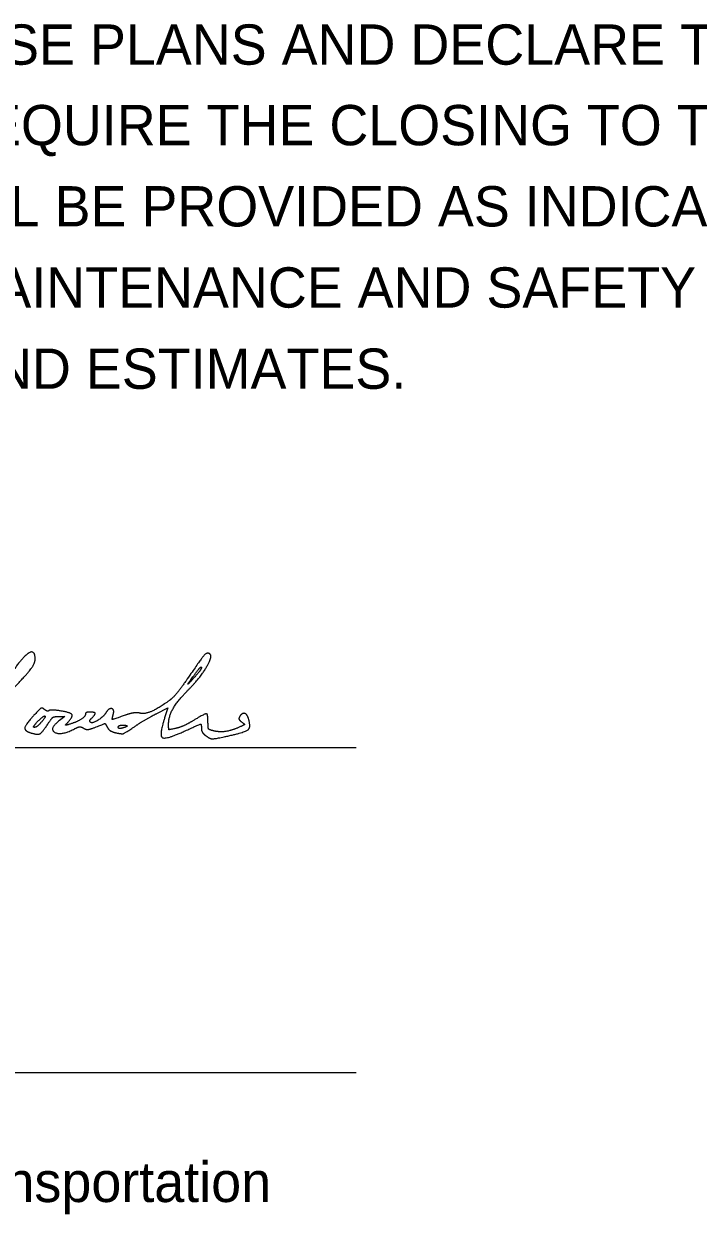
# Model space of a CAD drawing. Extents: x 0 to 44, y -23.8 to 22.
# Drawn here: x 26.858 to 29.2, y 6.74 to 10.877 of the extents above; entities that cross this region are included whole.
import ezdxf

# ---------------------------------------------------------------- set-up
doc = ezdxf.new("R2010")
doc.units = 0
for name, color, linetype in [('Default', 7, 'Continuous'), ('SH_Data', 7, 'Continuous'), ('SH_Text', 7, 'Continuous')]:
    doc.layers.add(name, color=color, linetype=linetype)

msp = doc.modelspace()

# ---------------------------------------------------------------- linework, layer by layer
at = {"layer": 'SH_Data'}
for p, q in [((24.5118, 8.362), (28.0118, 8.362)), ((24.5118, 7.2326), (28.0118, 7.2326))]:
    msp.add_line(p, q, dxfattribs=at)
at = {"layer": 'SH_Text'}
for points in [[(27.3194, 8.4803), (27.3581, 8.4995), (27.3466, 8.4648)], [(26.9786, 8.4699), (26.9995, 8.4698), (26.9812, 8.4557)]]:
    msp.add_lwpolyline(points, dxfattribs=at)
for points in [[(26.8969, 8.6691), (26.8969, 8.7104), (26.8352, 8.6573), (26.7842, 8.5722)], [(27.5031, 8.6878), (27.4935, 8.6937), (27.4735, 8.671), (27.421, 8.5943)], [(27.4322, 8.566), (27.471, 8.6052), (27.5149, 8.6805), (27.5031, 8.6878)], [(26.8047, 8.5499), (26.8641, 8.6119), (26.8969, 8.6543), (26.8969, 8.6691)], [(27.4508, 8.6066), (27.4263, 8.5793), (27.4293, 8.5872), (27.4579, 8.625)], [(27.4745, 8.6399), (27.4745, 8.6361), (27.4638, 8.6211), (27.4508, 8.6066)], [(27.4579, 8.625), (27.467, 8.6371), (27.4745, 8.6438), (27.4745, 8.6399)], [(27.3605, 8.4441), (27.3605, 8.4711), (27.393, 8.5264), (27.4322, 8.566)], [(27.421, 8.5943), (27.4005, 8.5644), (27.3742, 8.5332), (27.3626, 8.525)], [(27.3626, 8.525), (27.3218, 8.4962), (27.277, 8.4774), (27.2598, 8.4817)], [(26.9296, 8.4941), (26.9213, 8.501), (26.9136, 8.4968), (26.8928, 8.4741)], [(26.9447, 8.4901), (26.9422, 8.4875), (26.9354, 8.4894), (26.9296, 8.4941)], [(26.9839, 8.4896), (26.9649, 8.4924), (26.9473, 8.4926), (26.9447, 8.4901)], [(27.009, 8.448), (27.0291, 8.4691), (27.0201, 8.4841), (26.9839, 8.4896)], [(27.0869, 8.4853), (27.0785, 8.4853), (27.0717, 8.4823), (27.0717, 8.4786)], [(27.0931, 8.4642), (27.1064, 8.4774), (27.1041, 8.4853), (27.0869, 8.4853)], [(27.1424, 8.4827), (27.1336, 8.468), (27.0949, 8.4444), (27.089, 8.4502)], [(27.1683, 8.4777), (27.1729, 8.4953), (27.1523, 8.4993), (27.1424, 8.4827)], [(27.2598, 8.4817), (27.2504, 8.4841), (27.2277, 8.4807), (27.2094, 8.4742)], [(27.6375, 8.4636), (27.6325, 8.4793), (27.6151, 8.4824), (27.6068, 8.469)], [(26.8928, 8.4741), (26.8631, 8.4417), (26.8592, 8.4202), (26.8817, 8.4131)], [(26.8817, 8.4131), (26.905, 8.4057), (26.9218, 8.4144), (26.9406, 8.4435)], [(26.8944, 8.4321), (26.8901, 8.4321), (26.8946, 8.4406), (26.9044, 8.4511)], [(26.9159, 8.4474), (26.9083, 8.439), (26.8986, 8.4321), (26.8944, 8.4321)], [(26.9044, 8.4511), (26.9254, 8.4733), (26.9362, 8.4698), (26.9159, 8.4474)], [(26.9406, 8.4435), (26.9535, 8.4634), (26.9631, 8.4701), (26.9786, 8.4699)], [(26.9812, 8.4557), (26.9435, 8.4267), (26.9872, 8.4028), (27.0337, 8.427)], [(27.0185, 8.4438), (27.0029, 8.439), (27.0012, 8.4398), (27.009, 8.448)], [(27.0717, 8.4786), (27.0717, 8.47), (27.043, 8.4512), (27.0185, 8.4438)], [(27.089, 8.4502), (27.0863, 8.4529), (27.0881, 8.4592), (27.0931, 8.4642)], [(27.1091, 8.4339), (27.1385, 8.4455), (27.1406, 8.4454), (27.1477, 8.4321)], [(27.2094, 8.4742), (27.1667, 8.4592), (27.1635, 8.4594), (27.1683, 8.4777)], [(27.1857, 8.4328), (27.1857, 8.4366), (27.1925, 8.4397), (27.2009, 8.4397)], [(27.2009, 8.4397), (27.2092, 8.4397), (27.2161, 8.4384), (27.2161, 8.4368)], [(27.2415, 8.4344), (27.263, 8.449), (27.2981, 8.4697), (27.3194, 8.4803)], [(27.3466, 8.4648), (27.3266, 8.404), (27.3506, 8.3891), (27.4184, 8.4202)], [(27.3852, 8.4285), (27.362, 8.4236), (27.3605, 8.4246), (27.3605, 8.4441)], [(27.4464, 8.4559), (27.4263, 8.4437), (27.3988, 8.4314), (27.3852, 8.4285)], [(27.4184, 8.4202), (27.4685, 8.4431), (27.4745, 8.4439), (27.4745, 8.4272)], [(27.4973, 8.447), (27.4973, 8.4791), (27.4875, 8.4808), (27.4464, 8.4559)], [(27.5163, 8.42), (27.5014, 8.4238), (27.4973, 8.4296), (27.4973, 8.447)], [(27.5657, 8.402), (27.6271, 8.4156), (27.6473, 8.4329), (27.6375, 8.4636)], [(27.6068, 8.469), (27.6038, 8.4641), (27.6069, 8.4561), (27.6138, 8.4511)], [(27.6138, 8.4511), (27.6249, 8.443), (27.6243, 8.4412), (27.608, 8.4337)], [(27.0337, 8.427), (27.0469, 8.4339), (27.0565, 8.4346), (27.0653, 8.4293)], [(27.0653, 8.4293), (27.0742, 8.4239), (27.0871, 8.4253), (27.1091, 8.4339)], [(27.1477, 8.4321), (27.1518, 8.4244), (27.1658, 8.4158), (27.1787, 8.413)], [(27.1787, 8.413), (27.1981, 8.4087), (27.2094, 8.4126), (27.2415, 8.4344)], [(27.2009, 8.4299), (27.1925, 8.4277), (27.1857, 8.429), (27.1857, 8.4328)], [(27.2161, 8.4368), (27.2161, 8.4352), (27.2092, 8.4321), (27.2009, 8.4299)], [(27.4745, 8.4272), (27.4745, 8.4204), (27.4805, 8.4102), (27.4878, 8.4047)], [(27.4878, 8.4047), (27.5037, 8.3926), (27.5203, 8.392), (27.5657, 8.402)], [(27.608, 8.4337), (27.5802, 8.4211), (27.5375, 8.4147), (27.5163, 8.42)]]:
    msp.add_open_spline(points, degree=2, dxfattribs=at)

# ---------------------------------------------------------------- texts
at = {"layer": 'Default'}
for s, p in [('I HEREBY APPROVE THESE PLANS AND DECLARE THAT THE MAKING OF THIS', (24.5279, 10.735)), ('IMPROVEMENTS WILL REQUIRE THE CLOSING TO TRAFFIC OF THE HIGHWAY ', (24.5279, 10.455)), ('AND THAT DETOURS WILL BE PROVIDED AS INDICATED ON SHEET P.8.', (24.5199, 10.1729)), ('PROVISIONS FOR THE MAINTENANCE AND SAFETY OF TRAFFIC WILL BE SET', (24.5118, 9.8908)), ('FORTH ON THE PLANS AND ESTIMATES.', (24.5038, 9.6087))]:
    msp.add_text(s, height=0.14, dxfattribs=at).set_placement(p)
at = {"layer": 'SH_Text'}
msp.add_text('Director, Department of Transportation', height=0.14, dxfattribs=at).set_placement((24.5118, 6.7826))

doc.saveas('drawing.dxf')
